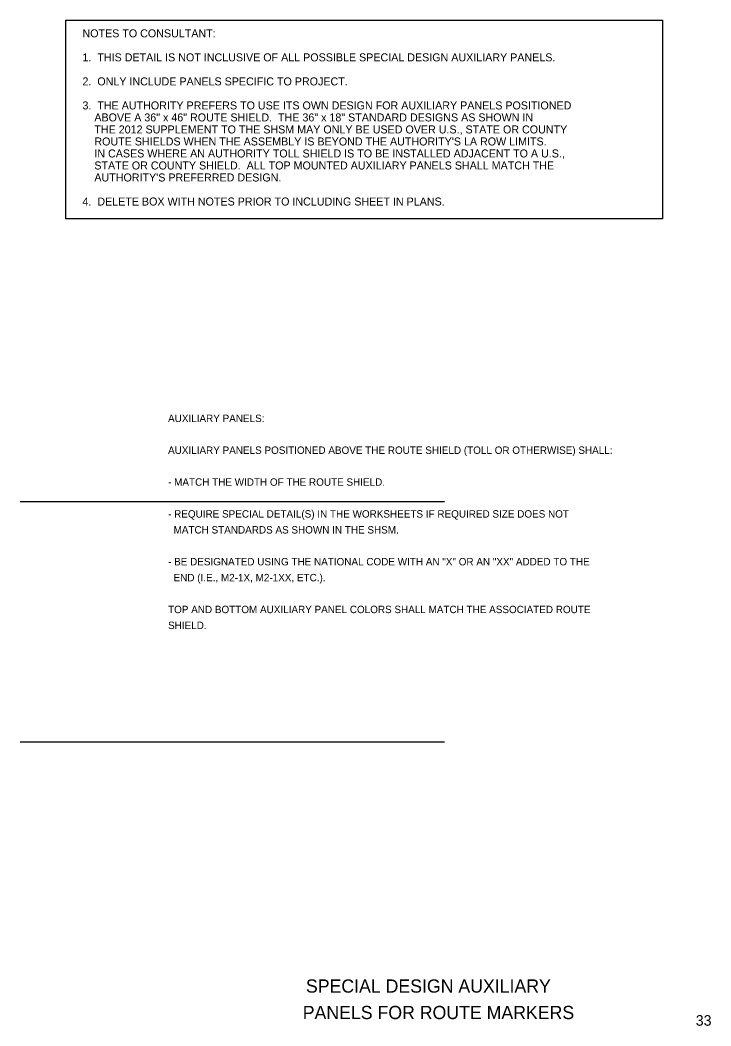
# Model space of a CAD drawing. Extents: x 60714 to 61340, y 8039 to 8429.
# Drawn here: x 61078.9 to 61339.8, y 8049.1 to 8429 of the extents above; entities that cross this region are included whole.
import ezdxf

# ---------------------------------------------------------------- set-up
doc = ezdxf.new("R2010")
doc.units = 0
for name, color, linetype in [('TextAlert', 7, 'Continuous'), ('TextMisc', 7, 'Continuous'), ('TextNotes', 7, 'Continuous'), ('TextShtNo', 7, 'Continuous')]:
    doc.layers.add(name, color=color, linetype=linetype)

msp = doc.modelspace()

# ---------------------------------------------------------------- linework, layer by layer
at = {"layer": 'TextAlert'}
msp.add_lwpolyline([(61096.18, 8428.97), (61321.59, 8428.97), (61321.59, 8353.95), (61096.18, 8353.95)], close=True, dxfattribs=at)
at = {"layer": 'TextNotes'}
for p, q in [((61078.86, 8247.22), (61239.14, 8247.22)), ((61239.14, 8156.31), (61078.86, 8156.31))]:
    msp.add_line(p, q, dxfattribs=at)

# ---------------------------------------------------------------- texts
at = {"layer": 'TextAlert'}
for s, p in [('NOTES TO CONSULTANT:', (61102.42, 8422.46)), ('1.  THIS DETAIL IS NOT INCLUSIVE OF ALL POSSIBLE SPECIAL DESIGN AUXILIARY PANELS.', (61102.42, 8413.39)), ('2.  ONLY INCLUDE PANELS SPECIFIC TO PROJECT.', (61102.42, 8404.31)), ('3.  THE AUTHORITY PREFERS TO USE ITS OWN DESIGN FOR AUXILIARY PANELS POSITIONED', (61102.42, 8395.24)), ('    ABOVE A 36" x 46" ROUTE SHIELD.  THE 36" x 18" STANDARD DESIGNS AS SHOWN IN', (61102.42, 8390.71)), ('    THE 2012 SUPPLEMENT TO THE SHSM MAY ONLY BE USED OVER U.S., STATE OR COUNTY', (61102.42, 8386.17)), ("    ROUTE SHIELDS WHEN THE ASSEMBLY IS BEYOND THE AUTHORITY'S LA ROW LIMITS.", (61102.42, 8381.63)), ('    IN CASES WHERE AN AUTHORITY TOLL SHIELD IS TO BE INSTALLED ADJACENT TO A U.S.,', (61102.42, 8377.1)), ('    STATE OR COUNTY SHIELD.  ALL TOP MOUNTED AUXILIARY PANELS SHALL MATCH THE', (61102.42, 8372.56)), ("    AUTHORITY'S PREFERRED DESIGN. ", (61102.42, 8368.03)), ('4.  DELETE BOX WITH NOTES PRIOR TO INCLUDING SHEET IN PLANS.', (61102.42, 8358.95))]:
    msp.add_text(s, height=3.024, dxfattribs=at).set_placement(p)
at = {"layer": 'TextMisc'}
for s, p in [('SPECIAL DESIGN AUXILIARY', (61186.84, 8061.67)), ('PANELS FOR ROUTE MARKERS', (61185.63, 8051.67))]:
    msp.add_text(s, height=5, rotation=360, dxfattribs=at).set_placement(p)
at = {"layer": 'TextNotes'}
for s, p in [('AUXILIARY PANELS:', (61134.76, 8277.17)), ('AUXILIARY PANELS POSITIONED ABOVE THE ROUTE SHIELD (TOLL OR OTHERWISE) SHALL:', (61134.76, 8265.14)), ('- MATCH THE WIDTH OF THE ROUTE SHIELD.', (61134.76, 8253.11)), ('- REQUIRE SPECIAL DETAIL(S) IN THE WORKSHEETS IF REQUIRED SIZE DOES NOT', (61134.76, 8241.08)), ('  MATCH STANDARDS AS SHOWN IN THE SHSM.', (61134.76, 8235.07)), ('- BE DESIGNATED USING THE NATIONAL CODE WITH AN "X" OR AN "XX" ADDED TO THE', (61134.76, 8223.04)), ('  END (I.E., M2-1X, M2-1XX, ETC.).', (61134.76, 8217.02)), ('TOP AND BOTTOM AUXILIARY PANEL COLORS SHALL MATCH THE ASSOCIATED ROUTE', (61134.76, 8205)), ('SHIELD.', (61134.76, 8198.98))]:
    msp.add_text(s, height=2.8, dxfattribs=at).set_placement(p)
at = {"layer": 'TextShtNo'}
msp.add_text('33', height=4, rotation=360, dxfattribs=at).set_placement((61334.11, 8049.17))

doc.saveas('drawing.dxf')
